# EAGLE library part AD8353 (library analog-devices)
1 MHz to 2.7 GHz RF Gain Block Source: AD8353.pdf
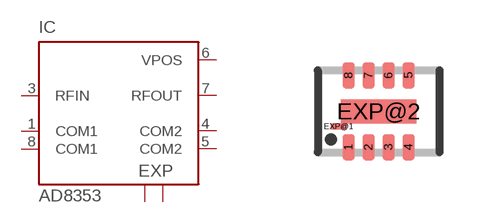
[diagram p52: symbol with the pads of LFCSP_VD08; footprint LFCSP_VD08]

Designator prefix IC

## AD8353 (MF: ALTERA CORPORATION; MPN: AD8353ACPZ-REEL7; OC_FARNELL: 1346356; OC_NEWARK: 59K6665)  [LFCSP_VD08]
1  COM1  in
3  RFIN  in
4  COM2  in
5  COM2  in
6  VPOS  pwr
7  RFOUT  out
8  COM1  in
EXP@1  EXP  in
EXP@2  EXP  in

## Footprint LFCSP_VD08 (pad centres in mm)
8-Lead Lead Frame Chip Scale Package [LFCSP_VD] 2 mm × 3 mm Body, Very Thin, Dual Lead CP-8-1 Source: AD8353.pdf
smd 0.3 x 0.65: 1 -0.75,-0.9; 2 -0.25,-0.9; 3 0.25,-0.9; 4 0.75,-0.9; 5 0.75,0.9; 6 0.25,0.9; 7 -0.25,0.9; 8 -0.75,0.9
smd 0.4 x 0.15: EXP@1 -1,-0.375
smd 1.89 x 0.6: EXP@2 0,0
